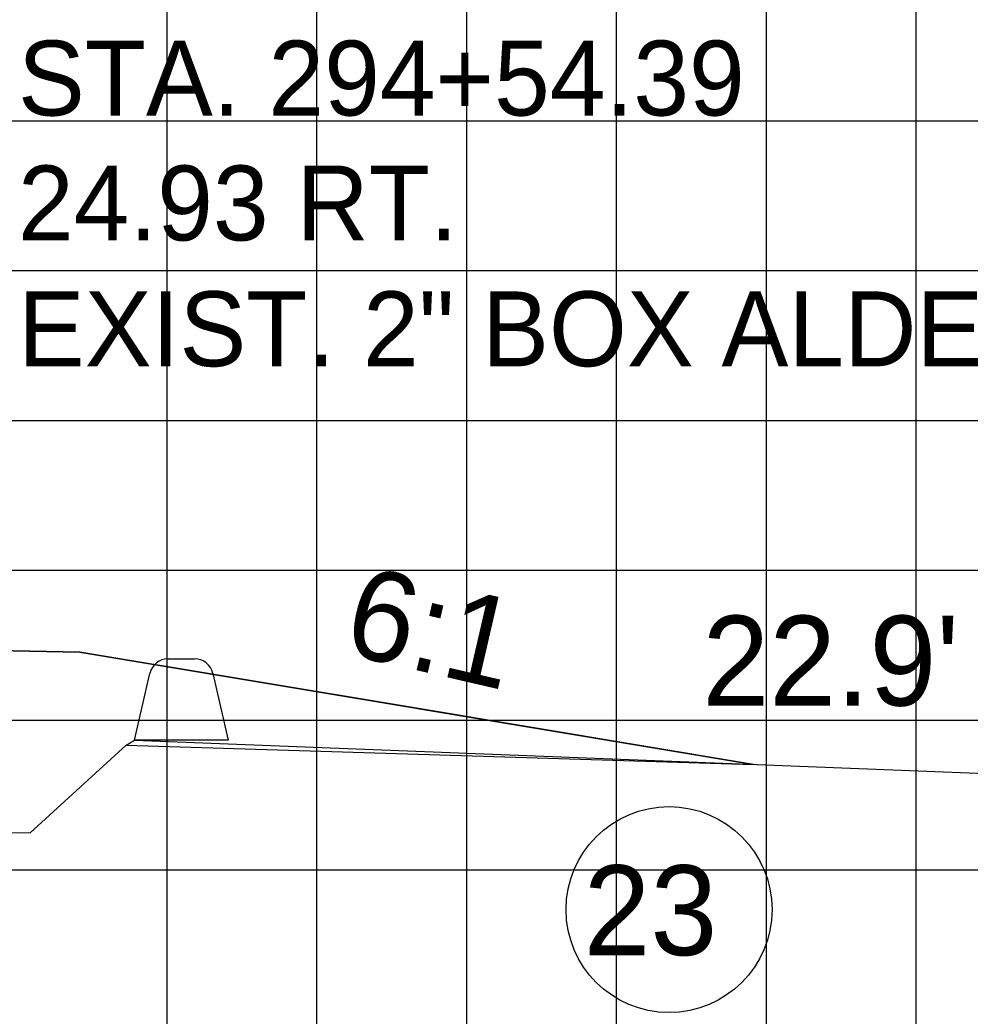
# Model space of a CAD drawing. Extents: x 859352 to 859522, y 366268 to 366378.
# Drawn here: x 859453.15 to 859459.49, y 366316.26 to 366322.91 of the extents above; entities that cross this region are included whole.
import ezdxf

# ---------------------------------------------------------------- set-up
doc = ezdxf.new("R2010")
doc.units = 0
for name, color, linetype in [('ANNOTATION', 7, 'Continuous'), ('D_Drainage_Text', 7, 'Continuous'), ('D_Roadway_FinishedGrade', 7, 'Continuous'), ('D_Text_Monospaced', 7, 'Continuous'), ('D_Text_Standard', 7, 'Continuous'), ('H_V ANNOTATION', 7, 'Continuous'), ('JUNK FILL', 7, 'Continuous'), ('MAJOR', 7, 'Continuous'), ('MINOR', 7, 'Continuous'), ('S_Curb_Type_3', 7, 'Continuous'), ('S_Roadway_Centerline', 7, 'Continuous')]:
    doc.layers.add(name, color=color, linetype=linetype)

msp = doc.modelspace()

# ---------------------------------------------------------------- linework, layer by layer
at = {"layer": 'D_Drainage_Text'}
msp.add_circle((859457.4795, 366316.9707), 0.6875, dxfattribs=at)
at = {"layer": 'D_Roadway_FinishedGrade'}
msp.add_line((859453.546, 366318.6895), (859458.0434, 366317.9399), dxfattribs=at)
msp.add_lwpolyline([(859450.5463, 366318.7495), (859453.546, 366318.6895)], dxfattribs=at)
at = {"layer": 'JUNK FILL'}
msp.add_lwpolyline([(859451.1294, 366317.5792), (859451.9326, 366317.5095), (859452.3261, 366317.489), (859453.2144, 366317.4832), (859453.8555, 366318.0678), (859458.0434, 366317.9399), (859455.7947, 366318.3147), (859453.546, 366318.6895), (859450.5463, 366318.7495), (859450.546, 366317.6297)], close=True, dxfattribs=at)
at = {"layer": 'MAJOR'}
for p, q in [((859455.1294, 366307.2365), (859455.1294, 366327.2365)), ((859365.1294, 366322.2365), (859505.1294, 366322.2365)), ((859365.1294, 366317.2365), (859505.1294, 366317.2365))]:
    msp.add_line(p, q, dxfattribs=at)
at = {"layer": 'MINOR'}
for p, q in [((859454.1294, 366307.2365), (859454.1294, 366327.2365)), ((859456.1294, 366307.2365), (859456.1294, 366327.2365)), ((859457.1294, 366307.2365), (859457.1294, 366327.2365)), ((859458.1294, 366307.2365), (859458.1294, 366327.2365)), ((859459.1294, 366307.2365), (859459.1294, 366327.2365)), ((859365.1294, 366321.2365), (859505.1294, 366321.2365)), ((859365.1294, 366320.2365), (859505.1294, 366320.2365)), ((859365.1294, 366319.2365), (859505.1294, 366319.2365)), ((859365.1294, 366318.2365), (859505.1294, 366318.2365))]:
    msp.add_line(p, q, dxfattribs=at)
at = {"layer": 'S_Curb_Type_3'}
for points in [[(859454.1364, 366318.6446), (859454.3125, 366318.6446)], [(859454.4343, 366318.5477), (859454.5369, 366318.1029), (859453.9119, 366318.1029), (859454.0146, 366318.5477)]]:
    msp.add_lwpolyline(points, dxfattribs=at)
for centre, start, end in [((859454.1364, 366318.5196), 90, 167.00538), ((859454.3125, 366318.5196), 12.99462, 90)]:
    msp.add_arc(centre, 0.125, start, end, dxfattribs=at)
at = {"layer": 'S_Roadway_Centerline'}
msp.add_lwpolyline([(859412.4198, 366318.3619), (859414.8357, 366318.5076), (859414.8959, 366318.5143), (859415.4194, 366318.5012), (859418.9658, 366318.4157), (859419.8012, 366318.3811), (859419.8657, 366318.3253), (859420.2885, 366317.8574), (859421.0178, 366317.8894), (859421.6219, 366317.9213), (859424.0518, 366318.0592), (859425.006, 366318.1017), (859426.7713, 366318.1358), (859435.8185, 366318.3085), (859444.5184, 366318.0869), (859445.568, 366318.0614), (859451.9326, 366317.5095), (859452.3261, 366317.489), (859453.2144, 366317.4832), (859453.8555, 366318.0678), (859453.9119, 366318.1029), (859458.1799, 366317.9345), (859464.0065, 366317.7058), (859478.0181, 366317.0147)], dxfattribs=at)

# ---------------------------------------------------------------- texts
at = {"layer": 'ANNOTATION'}
msp.add_text('6:1', height=0.6, rotation=346.9679, dxfattribs=at).set_placement((859455.2885, 366318.686))
at = {"layer": 'D_Text_Monospaced'}
for s, p in [('STA. 294+54.39', (859453.1337, 366322.2722)), ('24.93 RT.', (859453.1337, 366321.4382)), ('EXIST. 2" BOX ALDER', (859453.1337, 366320.5982))]:
    msp.add_text(s, height=0.49998, dxfattribs=at).set_placement(p)
at = {"layer": 'D_Text_Standard'}
msp.add_text("22.9'", height=0.6, dxfattribs=at).set_placement((859457.7018, 366318.3327))
at = {"layer": 'H_V ANNOTATION'}
msp.add_text('23', height=0.6, dxfattribs=at).set_placement((859456.9089, 366316.6663))

doc.saveas('drawing.dxf')
